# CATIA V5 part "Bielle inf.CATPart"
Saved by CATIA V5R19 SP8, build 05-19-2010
Part number: Bielle inf
Bounding box of the stored display mesh (mm): x 75 to 425, y -30 to 30, z -224.818 to -175.182
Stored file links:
  C:\Users\ThinkMotion\Desktop\EU_thinkMotion\iao\IAO_MMS_Groupe3\rdalborgo\rdalborgo\Bielle inf.CATPart
  C:\Users\ThinkMotion\Desktop\EU_thinkMotion\iao\IAO_MMS_Groupe3\rdalborgo\rdalborgo\rdalborgo.CATProduct
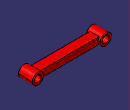
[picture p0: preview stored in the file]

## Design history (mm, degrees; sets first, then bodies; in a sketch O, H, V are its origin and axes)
External parameters (linked from other documents)
  `External.Axe inter diam` = 30 mm
  `External.Axe exter diam` = 50 mm
  `External.Demi hauteur bielle` = 15 mm
  `External.Longueur bielle` = 300 mm
  `External.Demi epaisseur bielle` = 20 mm
  `External.Demi epaisseur tete bielle` = 30 mm
Set1
  Plane1: linked copy from another document
  Point1 "D bielle": linked copy from another document
  Point2 "C bielle": linked copy from another document
  Line1: linked copy from another document
Body1 (main body)
  Sketch1 on Plane1, origin (0, 0, 0), H (-1, 0, 0), V (0, 0, 1)
    circle A1 centre (-100, -200) radius 15
    point P1 (-100, -200)
    circle A2 centre (-100, -200) radius 25
    point P2 (-100, -200)
    reference projected point E1 (-100, -200) from Point1
    circle A3 centre (-400, -200) radius 25
    point P3 (-400, -200)
    circle A4 centre (-400, -200) radius 15
    point P4 (-400, -200)
    reference projected point E2 (-400, -200) from Point2
    radius A1 = 15 {= `External.Axe inter diam` /2}
    radius A2 = 25 {= `External.Axe exter diam` /2}
    radius A3 = 25 {= `External.Axe exter diam` /2}
    radius A4 = 15 {= `External.Axe inter diam` /2}
    coincidence: P2 P1, P2 E1, P4 P3, P4 E2
  Pad1: profile Sketch1, direction (0, 1, 0), length 30 {= `External.Demi epaisseur tete bielle`}, mirrored extent
  Sketch2 on Plane1, origin (0, 0, 0), H (-1, 0, 0), V (0, 0, 1)
    line L1 (-385, -185) -> (-115, -185)
    line L2 (-115, -185) -> (-115, -215)
    line L3 (-115, -215) -> (-385, -215)
    line L4 (-385, -215) -> (-385, -185)
    reference projected line E1 (-100, -200) -> (-400, -200) from Line1
    reference projected point E2 (-400, -200) from Point2
    distance L1 L3 = 30 {= 2*`External.Demi hauteur bielle`}
    distance L1 E1 = 15 {= `External.Demi hauteur bielle`}
    distance L4 L2 = 270 {= `External.Longueur bielle` -`External.Axe inter diam`}
    distance L4 E2 = 15 {= `External.Axe inter diam` /2}
    horizontal: L1 H, L3 H
    vertical: L2 V, L4 V
  Pad2: profile Sketch2, direction (0, 1, 0), length 20 {= `External.Demi epaisseur bielle`}, mirrored extent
